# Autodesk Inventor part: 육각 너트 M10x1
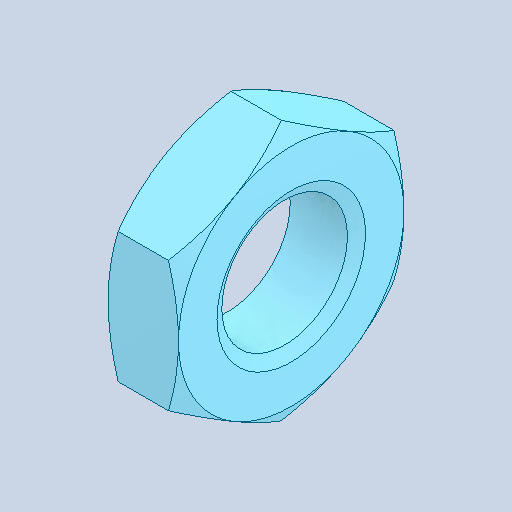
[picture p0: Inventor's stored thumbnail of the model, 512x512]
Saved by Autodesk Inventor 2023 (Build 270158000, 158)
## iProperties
Created: 2024-09
Part Number: 육각 너트 M10x1
Material: 강철, 연강
Description: 6각 너트 및 6각 가는 너트 - 이중 모따기
Document SubType Name: Modeling
Designer: home
Density: 7.85 g/cm^3
Appearance: 기본값
Author: jhkim
Sending System: Autodesk Inventor 2025
Preprocessor: ST-DEVELOPER v20
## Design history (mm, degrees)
node "육각 너트 M10x11"
node "솔리드1"
body "Solid1"
